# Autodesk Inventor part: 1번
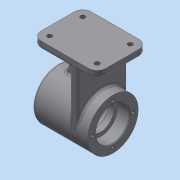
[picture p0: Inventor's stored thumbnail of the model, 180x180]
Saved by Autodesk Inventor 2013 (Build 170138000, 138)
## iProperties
Created: 2019-03
Part Number: 1번
Material: 일반
Document SubType Name: Modeling
Designer: dgall
Density: 1 g/cm^3
Author: dgall
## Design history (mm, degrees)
sketch "스케치1"
  geometry: L1 (0, 0)-(90, 0); L2 (90, 0)-(90, 70); L3 (90, 70)-(0, 70); L4 (0, 70)-(0, 0)
  constraints: 8 end point, 2 parallel, 1 horizontal, 1 perpendicular
  dimensions: "d0" = 90 distance of L2.end L3.end; "d2" = 70 distance of L1.end L2.end
extrude "돌출1" new body sketch "스케치1" distance "d3" = 10; taper "d4" = 0 deg
node "작업 평면1"
sketch "스케치2"
  geometry: L1 (90, 10)-(90, 0) reference; L2 (90, 0)-(0, 0) reference; L3 (0, 0)-(0, 10) reference; L4 (0, 10)-(90, 10) reference; L5 (77, -75)-(0, -75); L6 (0, -75)-(0, -110); L7 (0, -110)-(77, -110); L8 (77, -110)-(77, -98.5); L9 (77, -98.5)-(60, -98.5); L10 (60, -98.5)-(60, -93); L11 (60, -93)-(52, -93); L12 (52, -93)-(52, -102.5); L13 (52, -102.5)-(20, -102.5); L14 (20, -102.5)-(20, -92.5); L15 (20, -92.5)-(9, -92.5); L16 (9, -92.5)-(9, -88.5); L17 (9, -88.5)-(6, -88.5); L18 (6, -88.5)-(6, -75)
  constraints: 28 end point, 11 parallel, 3 perpendicular, 2 vertical alignment, 1 point on line, 1 vertical
  dimensions: "d5" = 77 distance of L6.end L7.end; "d7" = 85 distance between parallel lines of L4 L5; "d8" = 47 diameter of L9 L5; "d9" = 36 diameter of L11 L5; "d10" = 55 diameter of L13 L5; "d11" = 35 diameter of L15 L5; "d12" = 27 diameter of L17 L5; "d13" = 17 distance of L8.end L9.end; "d14" = 8 distance of L10.end L11.end; "d15" = 32 distance of L12.end L13.end; "d16" = 11 distance of L14.end L15.end; "d17" = 3 distance of L16.end L17.end; "d18" = 70 diameter of L7 L5
revolve "회전1" sketch "스케치2" stored, may be unused: angle "d19" = 90 deg
node "작업 평면2"
sketch "스케치3"
  geometry: L1 (0, 0)-(-10, 0) reference; L2 (-10, 0)-(-10, 70) reference; L3 (-10, 70)-(0, 70) reference; L4 (0, 70)-(0, 0) reference; L5 (75, 70)-(0, 70); L6 (75, 0)-(0, 0); L7 (0, 70)-(0, 0) reference; C1 r 23.5 at (75, 35) reference; C2 r 35 at (75, 35) reference; A1 r 35 centre (75, 35) between (75, 70) and (75, 0) reference
  constraints: 4 end point, 3 tangent, 2 perpendicular, 2 point on circle
extrude "돌출2" join sketch "스케치3" distance "d21" = 10; taper "d22" = 0 deg
sketch "스케치4"
  geometry: L1 (90, 10)-(90, 0) reference; L2 (90, 0)-(62, 0) reference; L3 (62, 0)-(62, -40) reference; L4 (62, -40)-(77, -40) reference; L5 (77, -40)-(77, -51.5) reference; L6 (77, -51.5)-(60, -51.5) reference; L7 (60, -51.5)-(60, -57) reference; L8 (60, -57)-(52, -57) reference; L9 (52, -57)-(52, -47.5) reference; L10 (52, -47.5)-(20, -47.5) reference; L11 (20, -47.5)-(20, -57.5) reference; L12 (20, -57.5)-(9, -57.5) reference; L13 (9, -57.5)-(9, -61.5) reference; L14 (9, -61.5)-(6, -61.5) reference; L15 (6, -61.5)-(6, -88.5) reference; L16 (6, -88.5)-(9, -88.5) reference; L17 (9, -88.5)-(9, -92.5) reference; L18 (9, -92.5)-(20, -92.5) reference; L19 (20, -92.5)-(20, -102.5) reference; L20 (20, -102.5)-(52, -102.5) reference; L21 (52, -102.5)-(52, -93) reference; L22 (52, -93)-(60, -93) reference; L23 (60, -93)-(60, -98.5) reference; L24 (60, -98.5)-(77, -98.5) reference; L25 (77, -98.5)-(77, -110) reference; L26 (77, -110)-(0, -110) reference; L27 (0, -110)-(0, -40) reference; L28 (0, -40)-(52, -40) reference; L29 (52, -40)-(52, 0) reference; L30 (52, 0)-(0, 0) reference; L31 (0, 0)-(0, 10) reference; L32 (0, 10)-(90, 10) reference; L33 (30, 0)-(15.441, -40)
  constraints: 2 end point, 1 point on line
  dimensions: "d26" = 70 deg angle of L30 L33; "d27" = 21.99996 distance from line of L29 L33.start; "d28" = 36.55877 distance from line of L29 L33.end
feature "리브1" sketch "스케치4" dims "d29" = 1, "d30" = 10, "d31" = 0, "d32" = 0, "d33" = 1, "d34" = 1
fillet "모깎기1" dims "d35" = 12
sketch "스케치5"
  geometry: L1 (-62, 0)-(-62, 70) reference; L2 (-78, 70)-(-62, 70) reference; L3 (-90, 12)-(-90, 58) reference; L4 (-62, 0)-(-78, 0) reference; L5 (-52, 0)-(-62, 0) reference; L6 (-52, 30)-(-52, 0) reference; L7 (-30, 30)-(-52, 30) reference; L8 (-30, 40)-(-30, 30) reference; L9 (-52, 40)-(-30, 40) reference; L10 (-52, 70)-(-52, 40) reference; L11 (-52, 70)-(-12, 70) reference; L12 (0, 58)-(0, 12) reference; L13 (-12, 0)-(-52, 0) reference; L14 (-62, 70)-(-52, 70) reference; A1 r 12 centre (-78, 12) between (-90, 12) and (-78, 0) reference; A2 r 12 centre (-78, 58) between (-78, 70) and (-90, 58) reference; A3 r 12 centre (-78, 58) between (-78, 70) and (-90, 58) reference; A4 r 12 centre (-78, 12) between (-90, 12) and (-78, 0) reference; A5 r 12 centre (-12, 58) between (0, 58) and (-12, 70) reference; A6 r 12 centre (-12, 12) between (-12, 0) and (0, 12) reference; 1 further point
hole "구멍1" sketch "스케치5" at (-12, 12), (-78, 12), (-78, 58), (-12, 58) diameter "d36" = 6.6; stored, may be unused: countersink angle "d40" = 90 deg, drill point angle "d42" = 118 deg; dims "d37" = 6, "d38" = 16, "d39" = 2, "d41" = 8
sketch "스케치6" dims "d43" = 56
  geometry: C1 r 35 at (0, 0) reference; C2 r 23.5 at (0, 0) reference; 3 further points
  constraints: 2 vertical alignment, 1 coincident, 2 other
hole "구멍2" sketch "스케치6" at (0, 28) diameter "d45" = 4.134; stored, may be unused: countersink angle "d49" = 90 deg, drill point angle "d51" = 118 deg; dims "d46" = 11, "d47" = 16, "d48" = 2, "d50" = 14
chamfer "모따기1" distance "d55" = 1; stored, may be unused: second distance "d56" = 2, angle "d57" = 45 deg
fillet "모깎기2" dims "d58" = 3
fillet "모깎기3" dims "d59" = 3
fillet "모깎기4" dims "d60" = 3
fillet "모깎기5" dims "d61" = 3
node "솔리드1"
pattern_circular "원형 패턴1" dims angle "d53" = 360 deg
node "절단 모서리 투영1"
node "절단 모서리 투영2"
node "절단 모서리 투영3"
node "절단 모서리 투영4"
other parameters: "d20" = -28
